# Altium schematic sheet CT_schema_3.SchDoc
size 187 x 159 mm
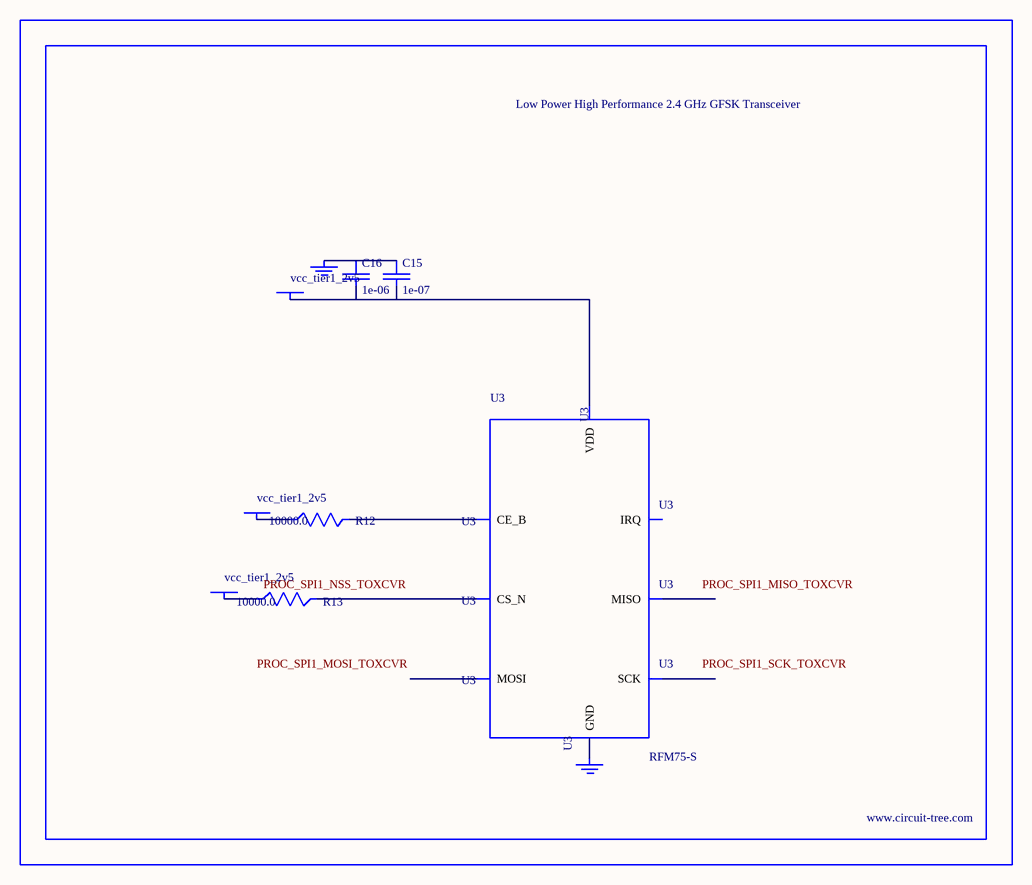
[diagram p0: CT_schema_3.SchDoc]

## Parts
BORDER2  (no value)
C15  1e-07  [C0402]
C16  1e-06  [C0603]
GND_INSTANCE_2_0  (no value)
GND_INSTANCE_2_1  (no value)
POWER_INSTANCE_2_0  vcc_tier1_2v5
POWER_INSTANCE_2_1  vcc_tier1_2v5
POWER_INSTANCE_2_2  vcc_tier1_2v5
R12  10000.0  [R0603]
R13  10000.0  [R0603]
U3  RFM75-S  [RFM75-S]

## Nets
NetC15_1: C15.1 C16.1 GND_INSTANCE_2_0.0(GND)
NetC15_2: C15.2 C16.2 POWER_INSTANCE_2_0.0(PWR) U3.2(VDD)
NetGND_INSTANCE_2_1_0: GND_INSTANCE_2_1.0(GND) U3.1(GND)
NetPOWER_INSTANCE_2_1_0: POWER_INSTANCE_2_1.0(PWR) R12.1
NetPOWER_INSTANCE_2_2_0: POWER_INSTANCE_2_2.0(PWR) R13.1
NetR12_2: R12.2 U3.3(CE_B)
NetR13_2: R13.2 U3.4(CS_N)

Not connected (* = marked no-connect by the designer): U3 5(SCK) 6(MOSI) 7(MISO) 8(IRQ)

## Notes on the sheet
- Labels drawn without touching a wire or pin: PROC_SPI1_MISO_TOXCVR, PROC_SPI1_MOSI_TOXCVR, PROC_SPI1_NSS_TOXCVR, PROC_SPI1_SCK_TOXCVR

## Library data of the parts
BORDER2 = BORDER_PAGE2
C15 = C0402C104K3RACTU
C16 = C0603C105K3RACTU
GND_INSTANCE_2_0 GND_INSTANCE_2_1 = GND
POWER_INSTANCE_2_0-POWER_INSTANCE_2_2 = PWR
R12 R13 = RC0603JR-0710KL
